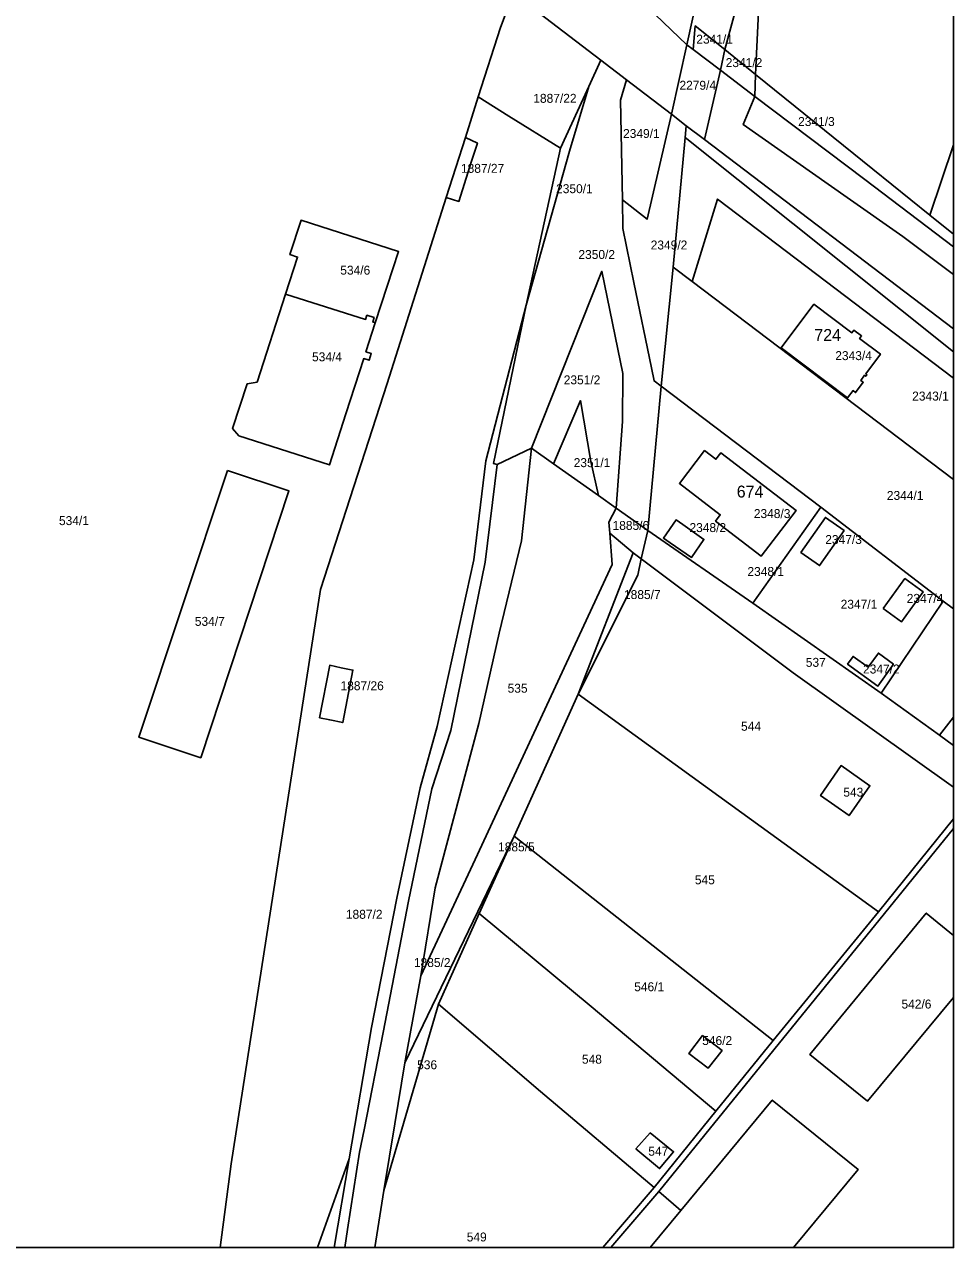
# Model space of a CAD drawing. Extents: x -561316 to -560969, y -1077679 to -1077341.
# Drawn here: x -561124.4 to -560968.7, y -1077679.3 to -1077474.3 of the extents above; entities that cross this region are included whole.
import ezdxf

# ---------------------------------------------------------------- set-up
doc = ezdxf.new("R2010")
doc.units = 0
for name, color, linetype in [('Adresní místo-text', 7, 'Continuous'), ('Parcela-polygon', 7, 'Continuous'), ('Parcela-text', 7, 'Continuous')]:
    doc.layers.add(name, color=color, linetype=linetype)

msp = doc.modelspace()

# ---------------------------------------------------------------- linework, layer by layer
at = {"layer": 'Parcela-polygon'}
for p, q in [((-560968.69, -1077494.47), (-560968.69, -1077454.77)), ((-560968.69, -1077509.45), (-560968.69, -1077494.47)), ((-560968.69, -1077511.52), (-560968.69, -1077509.45)), ((-560968.69, -1077516.19), (-560968.69, -1077511.52)), ((-560968.69, -1077525.27), (-560968.69, -1077516.19)), ((-560968.69, -1077529.13), (-560968.69, -1077525.27)), ((-560968.69, -1077533.59), (-560968.69, -1077529.13)), ((-560968.69, -1077550.53), (-560968.69, -1077533.59)), ((-560968.69, -1077572.24), (-560968.69, -1077550.53)), ((-560968.69, -1077590.42), (-560968.69, -1077572.24)), ((-560968.69, -1077595.14), (-560968.69, -1077590.42)), ((-560968.69, -1077602.11), (-560968.69, -1077595.14)), ((-560968.69, -1077607.47), (-560968.69, -1077602.11)), ((-560968.69, -1077609.05), (-560968.69, -1077607.47)), ((-560968.69, -1077627.01), (-560968.69, -1077609.05)), ((-560968.69, -1077637.4), (-560968.69, -1077627.01)), ((-561154.34, -1077679.32), (-561091.55, -1077679.32)), ((-561091.55, -1077679.32), (-561075.28, -1077679.32)), ((-561075.28, -1077679.32), (-561072.47, -1077679.32)), ((-561072.47, -1077679.32), (-561070.69, -1077679.32)), ((-561070.69, -1077679.32), (-561065.66, -1077679.32)), ((-561065.66, -1077679.32), (-561027.42, -1077679.32)), ((-561027.42, -1077679.32), (-561026.1, -1077679.32)), ((-561026.1, -1077679.32), (-561019.54, -1077679.32)), ((-561019.54, -1077679.32), (-560995.5, -1077679.32))]:
    msp.add_line(p, q, dxfattribs=at)
for points in [[(-561049.4, -1077448.02), (-561061.67, -1077436.19), (-561067.96, -1077422.91), (-561068.64, -1077418.05), (-561071.01, -1077414.57), (-561080.63, -1077400.23), (-561083.3, -1077402.66), (-561077.2, -1077431.15), (-561071.96, -1077441.19), (-561061.08, -1077454.04), (-561042.48, -1077469.05), (-561038.9, -1077471.78), (-561038.17, -1077472.34), (-561027.8, -1077480.27), (-561023.49, -1077483.56), (-561015.97, -1077489.32), (-561013.39, -1077477.66), (-561019.96, -1077471.39), (-561024.53, -1077467.03), (-561034.02, -1077457.97), (-561034.74, -1077457.28), (-561041.8, -1077454.56)], [(-560999.92, -1077421.13), (-561004.7, -1077438.43), (-561008.32, -1077441.67), (-561011.3, -1077441.2), (-561015.12, -1077440.58), (-561022.46, -1077462.15), (-561024.53, -1077467.03), (-561019.96, -1077471.39), (-561013.39, -1077477.66), (-561011.59, -1077469.52), (-561006.86, -1077448.2), (-561004.74, -1077446.51), (-560998.49, -1077422.25)], [(-561002.84, -1077444.99), (-561004.74, -1077446.51), (-561006.86, -1077448.2), (-561011.59, -1077469.52), (-561013.39, -1077477.66), (-561012.31, -1077478.48), (-561011.96, -1077474.5), (-561007.03, -1077478.49), (-561000.5, -1077454.6), (-561000.11, -1077443.84)], [(-561007.03, -1077478.49), (-561001.87, -1077482.65), (-561000.5, -1077454.6)], [(-561042.48, -1077469.05), (-561044.6, -1077474.75), (-561048.31, -1077486.41), (-561043.17, -1077489.63), (-561034.56, -1077495.01), (-561029.82, -1077484.67), (-561027.8, -1077480.27), (-561038.17, -1077472.34), (-561038.9, -1077471.78)], [(-561011.96, -1077474.5), (-561012.31, -1077478.48), (-561007.76, -1077481.93), (-561007.03, -1077478.49)], [(-561012.31, -1077478.48), (-561013.39, -1077477.66), (-561015.97, -1077489.32), (-561013.46, -1077491.24), (-561010.39, -1077493.57), (-561007.76, -1077481.93)], [(-561007.76, -1077481.93), (-561001.97, -1077486.32), (-561001.87, -1077482.65), (-561007.03, -1077478.49)], [(-561040.3, -1077521.34), (-561045.79, -1077547.85), (-561045.15, -1077548.03), (-561039.41, -1077545.32), (-561027.61, -1077515.65), (-561024.94, -1077528.68), (-561024.1, -1077532.76), (-561024.14, -1077540.85), (-561025.24, -1077555.34), (-561019.93, -1077559.09), (-561017.67, -1077534.93), (-561018.86, -1077534.02), (-561019.31, -1077531.84), (-561022.24, -1077517.52), (-561024.1, -1077508.46), (-561024.18, -1077503.66), (-561024.47, -1077486.94), (-561023.49, -1077483.56), (-561027.8, -1077480.27), (-561029.82, -1077484.67), (-561033.06, -1077495.53)], [(-561023.49, -1077483.56), (-561024.47, -1077486.94), (-561024.18, -1077503.66), (-561020.04, -1077506.91), (-561015.97, -1077489.32)], [(-561034.56, -1077495.01), (-561040.3, -1077521.34), (-561033.06, -1077495.53), (-561029.82, -1077484.67)], [(-561020.04, -1077506.91), (-561024.18, -1077503.66), (-561024.1, -1077508.46), (-561022.24, -1077517.52), (-561019.31, -1077531.84), (-561018.86, -1077534.02), (-561017.67, -1077534.93), (-561015.64, -1077514.95), (-561013.63, -1077493.22), (-561013.46, -1077491.24), (-561015.97, -1077489.32)], [(-561050.47, -1077493.22), (-561053.67, -1077503.25), (-561051.57, -1077503.92), (-561049.72, -1077498.1), (-561049.43, -1077497.19), (-561048.47, -1077494.15)], [(-561061.68, -1077512.35), (-561078, -1077507.1), (-561079.88, -1077512.86), (-561078.6, -1077513.27), (-561080.62, -1077519.46), (-561067.2, -1077523.73), (-561066.97, -1077523.03), (-561065.77, -1077523.41), (-561066.01, -1077524.13), (-561065.57, -1077524.27), (-561063.56, -1077518.16)], [(-561039.41, -1077545.32), (-561035.74, -1077547.92), (-561031.2, -1077537.32), (-561029.46, -1077547.55), (-561028.18, -1077553.26), (-561025.24, -1077555.34), (-561024.14, -1077540.85), (-561024.1, -1077532.76), (-561024.94, -1077528.68), (-561027.61, -1077515.65)], [(-561066.25, -1077529.44), (-561067.15, -1077529.15), (-561065.57, -1077524.27), (-561066.01, -1077524.13), (-561065.77, -1077523.41), (-561066.97, -1077523.03), (-561067.2, -1077523.73), (-561080.62, -1077519.46), (-561085.39, -1077534.21), (-561087.06, -1077534.53), (-561089.47, -1077542.01), (-561088.41, -1077543.24), (-561073.26, -1077548.12), (-561070.5, -1077539.52), (-561067.51, -1077530.27), (-561066.6, -1077530.56)], [(-560985.38, -1077525.51), (-560985.71, -1077525.95), (-560992.07, -1077521.16), (-560997.57, -1077528.47), (-560986.43, -1077536.87), (-560985.53, -1077535.66), (-560985.11, -1077535.97), (-560983.82, -1077534.25), (-560984.24, -1077533.94), (-560983.59, -1077533.08), (-560983.39, -1077533.25), (-560983.2, -1077532.98), (-560983.39, -1077532.82), (-560980.94, -1077529.54), (-560984.42, -1077526.92), (-560984.09, -1077526.48)], [(-561017.67, -1077534.93), (-561019.93, -1077559.09), (-561002.33, -1077571.3), (-560990.94, -1077555.2)], [(-561031.2, -1077537.32), (-561035.74, -1077547.92), (-561028.18, -1077553.26), (-561029.46, -1077547.55)], [(-561026.45, -1077557.71), (-561025.24, -1077555.34), (-561028.18, -1077553.26), (-561035.74, -1077547.92), (-561039.41, -1077545.32), (-561041.08, -1077560.86), (-561044.81, -1077576.33), (-561048.24, -1077591.47), (-561055.56, -1077618.99), (-561057.92, -1077633.79), (-561048.86, -1077614.29), (-561025.87, -1077564.82), (-561026.3, -1077559.58)], [(-561014.61, -1077551.21), (-561010.4, -1077545.71), (-561008.49, -1077547.17), (-561007.68, -1077546.09), (-560995.08, -1077555.74), (-561000.94, -1077563.41), (-561008.56, -1077557.54), (-561007.78, -1077556.47)], [(-561008.49, -1077547.17), (-561010.4, -1077545.71), (-561014.61, -1077551.21), (-561007.78, -1077556.47), (-561008.56, -1077557.54), (-561000.94, -1077563.41), (-560995.08, -1077555.74), (-561007.68, -1077546.09)], [(-561090.35, -1077549.03), (-561105.17, -1077593.77), (-561094.83, -1077597.2), (-561080.04, -1077552.47)], [(-561025.24, -1077555.34), (-561026.45, -1077557.71), (-561026.3, -1077559.58), (-561022.35, -1077562.87), (-561021.01, -1077563.88), (-561019.93, -1077559.09)], [(-561002.33, -1077571.3), (-560980.81, -1077586.39), (-560970.44, -1077570.95), (-560990.94, -1077555.2)], [(-561012.59, -1077563.63), (-561016.16, -1077561.18), (-561017.3, -1077560.39), (-561015.17, -1077557.33), (-561014.04, -1077558.12), (-561010.5, -1077560.61)], [(-561015.17, -1077557.33), (-561017.3, -1077560.39), (-561016.16, -1077561.18), (-561012.59, -1077563.63), (-561010.5, -1077560.61), (-561014.04, -1077558.12)], [(-560987.03, -1077559.11), (-560991.13, -1077564.98), (-560994.25, -1077562.77), (-560990.16, -1077556.92)], [(-560994.25, -1077562.77), (-560991.13, -1077564.98), (-560987.03, -1077559.11), (-560990.16, -1077556.92)], [(-561048.86, -1077614.29), (-561057.92, -1077633.79), (-561060.6, -1077648.34), (-561042.32, -1077610.36), (-561031.57, -1077586.54), (-561022.35, -1077562.87), (-561026.3, -1077559.58), (-561025.87, -1077564.82)], [(-561022.35, -1077562.87), (-561031.57, -1077586.54), (-561021.61, -1077566.57), (-561021.01, -1077563.88)], [(-560980.47, -1077572.19), (-560976.83, -1077567.17), (-560973.76, -1077569.39), (-560977.39, -1077574.41)], [(-560980.47, -1077572.19), (-560977.39, -1077574.41), (-560973.76, -1077569.39), (-560976.83, -1077567.17)], [(-560981.37, -1077585.19), (-560986.44, -1077581.49), (-560985.51, -1077580.21), (-560983.01, -1077582.04), (-560981.27, -1077579.66), (-560978.75, -1077581.53)], [(-560986.44, -1077581.49), (-560981.37, -1077585.19), (-560978.75, -1077581.53), (-560981.27, -1077579.66), (-560983.01, -1077582.04), (-560985.51, -1077580.21)], [(-561074.93, -1077590.51), (-561073.21, -1077590.87), (-561071.02, -1077591.32), (-561069.31, -1077582.52), (-561071.29, -1077582.11), (-561073.21, -1077581.71)], [(-561008.03, -1077603.66), (-561031.57, -1077586.54), (-561042.32, -1077610.36), (-561021.9, -1077626.43), (-560998.9, -1077644.59), (-560981.28, -1077623.05)], [(-560990.97, -1077603.55), (-560986.18, -1077606.89), (-560982.7, -1077601.89), (-560987.52, -1077598.53)], [(-561064.14, -1077669.78), (-561055, -1077638.52), (-561048.19, -1077623.34), (-561042.32, -1077610.36), (-561060.6, -1077648.34), (-561062.29, -1077658.56)], [(-561021.9, -1077626.43), (-561042.32, -1077610.36), (-561048.19, -1077623.34), (-561029.43, -1077638.93), (-561008.51, -1077656.44), (-560998.9, -1077644.59)], [(-561029.43, -1077638.93), (-561048.19, -1077623.34), (-561055, -1077638.52), (-561037.9, -1077653.16), (-561018.85, -1077669.25), (-561008.51, -1077656.44)], [(-561009.82, -1077649.25), (-561013.05, -1077646.78), (-561010.74, -1077643.79), (-561007.47, -1077646.31)], [(-561010.74, -1077643.79), (-561013.05, -1077646.78), (-561009.82, -1077649.25), (-561007.47, -1077646.31)], [(-561021.9, -1077662.77), (-561017.93, -1077666.08), (-561015.59, -1077663.27), (-561019.5, -1077660.1)], [(-561015.59, -1077663.27), (-561017.93, -1077666.08), (-561021.9, -1077662.77), (-561019.5, -1077660.1)]]:
    msp.add_lwpolyline(points, close=True, dxfattribs=at)
for points in [[(-561091.55, -1077679.32), (-561089.7, -1077665.29), (-561074.75, -1077568.98), (-561063.6, -1077534.48), (-561053.67, -1077503.25), (-561050.47, -1077493.22), (-561048.31, -1077486.41), (-561044.6, -1077474.75), (-561042.48, -1077469.05), (-561061.08, -1077454.04), (-561071.96, -1077441.19), (-561077.2, -1077431.15), (-561083.3, -1077402.66), (-561097.85, -1077410.62), (-561118.92, -1077426.82), (-561123.47, -1077428.97), (-561141.46, -1077444.02)], [(-560968.69, -1077454.77), (-560988.77, -1077442.39), (-560995.41, -1077441.87), (-560997.54, -1077442.76), (-561000.5, -1077454.6), (-561001.87, -1077482.65), (-560982.23, -1077498.52), (-560972.64, -1077506.26), (-560968.69, -1077494.47)], [(-560968.69, -1077516.19), (-560977.16, -1077509.84), (-560986.49, -1077503.29), (-561003.96, -1077491.02), (-561001.97, -1077486.32), (-561007.76, -1077481.93), (-561010.39, -1077493.57), (-560968.69, -1077525.27)], [(-560968.69, -1077509.45), (-560972.64, -1077506.26), (-560982.23, -1077498.52), (-561001.87, -1077482.65), (-561001.97, -1077486.32), (-560983.57, -1077500.25), (-560968.69, -1077511.52)], [(-560968.69, -1077511.52), (-560983.57, -1077500.25), (-561001.97, -1077486.32), (-561003.96, -1077491.02), (-560986.49, -1077503.29), (-560977.16, -1077509.84), (-560968.69, -1077516.19)], [(-561075.28, -1077679.32), (-561069.95, -1077664.47), (-561066.21, -1077642.45), (-561061.99, -1077620.72), (-561058.03, -1077602.23), (-561055.23, -1077591.99), (-561049.05, -1077564.01), (-561047.07, -1077547.44), (-561040.3, -1077521.34), (-561034.56, -1077495.01), (-561043.17, -1077489.63), (-561048.31, -1077486.41), (-561050.47, -1077493.22), (-561048.47, -1077494.15), (-561049.43, -1077497.19), (-561049.72, -1077498.1), (-561051.57, -1077503.92), (-561053.67, -1077503.25), (-561063.6, -1077534.48), (-561074.75, -1077568.98), (-561089.7, -1077665.29), (-561091.55, -1077679.32)], [(-560968.69, -1077525.27), (-561010.39, -1077493.57), (-561013.46, -1077491.24), (-561013.63, -1077493.22), (-560968.69, -1077529.13)], [(-560968.69, -1077529.13), (-561013.63, -1077493.22), (-561015.64, -1077514.95), (-561012.48, -1077517.35), (-561008.23, -1077503.55), (-560968.69, -1077533.59)], [(-560968.69, -1077494.47), (-560972.64, -1077506.26), (-560968.69, -1077509.45)], [(-560968.69, -1077533.59), (-561008.23, -1077503.55), (-561012.48, -1077517.35), (-560968.69, -1077550.53)], [(-561078, -1077507.1), (-561061.68, -1077512.35), (-561063.56, -1077518.16), (-561065.57, -1077524.27), (-561067.15, -1077529.15), (-561066.25, -1077529.44), (-561066.6, -1077530.56), (-561067.51, -1077530.27), (-561070.5, -1077539.52), (-561073.26, -1077548.12), (-561088.41, -1077543.24), (-561089.47, -1077542.01), (-561087.06, -1077534.53), (-561085.39, -1077534.21), (-561080.62, -1077519.46), (-561078.6, -1077513.27), (-561079.88, -1077512.86), (-561078, -1077507.1)], [(-560968.69, -1077550.53), (-561012.48, -1077517.35), (-561015.64, -1077514.95), (-561017.67, -1077534.93), (-560990.94, -1077555.2), (-560970.44, -1077570.95), (-560968.69, -1077572.24)], [(-560984.09, -1077526.48), (-560984.42, -1077526.92), (-560980.94, -1077529.54), (-560983.39, -1077532.82), (-560983.2, -1077532.98), (-560983.39, -1077533.25), (-560983.59, -1077533.08), (-560984.24, -1077533.94), (-560983.82, -1077534.25), (-560985.11, -1077535.97), (-560985.53, -1077535.66), (-560986.43, -1077536.87), (-560997.57, -1077528.47), (-560992.07, -1077521.16), (-560985.71, -1077525.95), (-560985.38, -1077525.51), (-560984.09, -1077526.48)], [(-561070.69, -1077679.32), (-561070.22, -1077676.28), (-561068.21, -1077663.34), (-561067.46, -1077659.56), (-561064.23, -1077643.29), (-561060, -1077621.24), (-561056.11, -1077602.43), (-561052.89, -1077592.64), (-561047.16, -1077564.4), (-561045.15, -1077548.03), (-561045.79, -1077547.85), (-561040.3, -1077521.34), (-561047.07, -1077547.44), (-561049.05, -1077564.01), (-561055.23, -1077591.99), (-561058.03, -1077602.23), (-561061.99, -1077620.72), (-561066.21, -1077642.45), (-561069.95, -1077664.47), (-561072.47, -1077679.32)], [(-561065.66, -1077679.32), (-561064.14, -1077669.78), (-561062.29, -1077658.56), (-561060.6, -1077648.34), (-561057.92, -1077633.79), (-561055.56, -1077618.99), (-561048.24, -1077591.47), (-561044.81, -1077576.33), (-561041.08, -1077560.86), (-561039.41, -1077545.32), (-561045.15, -1077548.03), (-561047.16, -1077564.4), (-561052.89, -1077592.64), (-561056.11, -1077602.43), (-561060, -1077621.24), (-561064.23, -1077643.29), (-561067.46, -1077659.56), (-561068.21, -1077663.34), (-561070.22, -1077676.28), (-561070.69, -1077679.32)], [(-561090.35, -1077549.03), (-561080.04, -1077552.47), (-561094.83, -1077597.2), (-561105.17, -1077593.77), (-561090.35, -1077549.03)], [(-560968.69, -1077595.14), (-560971.06, -1077593.43), (-560980.81, -1077586.39), (-561002.33, -1077571.3), (-561019.93, -1077559.09), (-561021.01, -1077563.88), (-560995.54, -1077582.99), (-560968.69, -1077602.11)], [(-560968.69, -1077602.11), (-560995.54, -1077582.99), (-561021.01, -1077563.88), (-561021.61, -1077566.57), (-561031.57, -1077586.54), (-561008.03, -1077603.66), (-560981.28, -1077623.05), (-560968.69, -1077607.47)], [(-560968.69, -1077572.24), (-560970.44, -1077570.95), (-560980.81, -1077586.39), (-560971.06, -1077593.43), (-560968.69, -1077590.42)], [(-561074.93, -1077590.51), (-561073.21, -1077581.71), (-561071.29, -1077582.11), (-561069.31, -1077582.52), (-561071.02, -1077591.32), (-561073.21, -1077590.87), (-561074.93, -1077590.51)], [(-560968.69, -1077590.42), (-560971.06, -1077593.43), (-560968.69, -1077595.14)], [(-560986.18, -1077606.89), (-560990.97, -1077603.55), (-560987.52, -1077598.53), (-560982.7, -1077601.89), (-560986.18, -1077606.89)], [(-560968.69, -1077607.47), (-560981.28, -1077623.05), (-560998.9, -1077644.59), (-561008.51, -1077656.44), (-561018.85, -1077669.25), (-561027.42, -1077679.32)], [(-561026.1, -1077679.32), (-561018.09, -1077669.9), (-560968.69, -1077609.05)], [(-560968.69, -1077609.05), (-561018.09, -1077669.9), (-561014.38, -1077673.09), (-560999.06, -1077654.59), (-560984.66, -1077666.25), (-560995.5, -1077679.32)], [(-560968.69, -1077627.01), (-560973.25, -1077623.25), (-560992.78, -1077646.93), (-560983.08, -1077654.78), (-560968.69, -1077637.4)], [(-560968.69, -1077637.4), (-560983.08, -1077654.78), (-560992.78, -1077646.93), (-560973.25, -1077623.25), (-560968.69, -1077627.01)], [(-560995.5, -1077679.32), (-560968.69, -1077679.32), (-560968.69, -1077637.4)], [(-561027.42, -1077679.32), (-561018.85, -1077669.25), (-561037.9, -1077653.16), (-561055, -1077638.52), (-561064.14, -1077669.78), (-561065.66, -1077679.32)], [(-560995.5, -1077679.32), (-560984.66, -1077666.25), (-560999.06, -1077654.59), (-561014.38, -1077673.09), (-561019.54, -1077679.32)], [(-561072.47, -1077679.32), (-561069.95, -1077664.47), (-561075.28, -1077679.32)], [(-561019.54, -1077679.32), (-561014.38, -1077673.09), (-561018.09, -1077669.9), (-561026.1, -1077679.32)]]:
    msp.add_lwpolyline(points, dxfattribs=at)

# ---------------------------------------------------------------- texts
at = {"layer": 'Adresní místo-text'}
for s, p in [('724', (-560992.01, -1077527.33)), ('674', (-561005.01, -1077553.58))]:
    msp.add_text(s, height=2, dxfattribs=at).set_placement(p)
at = {"layer": 'Parcela-text'}
for s, p in [('2341/1', (-561011.79, -1077477.48)), ('2341/2', (-561006.86, -1077481.41)), ('2279/4', (-561014.61, -1077485.21)), ('1887/22', (-561039.1, -1077487.4)), ('2341/3', (-560994.73, -1077491.29)), ('2349/1', (-561024.06, -1077493.3)), ('1887/27', (-561051.22, -1077499.14)), ('2350/1', (-561035.28, -1077502.55)), ('2349/2', (-561019.43, -1077511.99)), ('2350/2', (-561031.54, -1077513.58)), ('534/6', (-561071.44, -1077516.21)), ('534/4', (-561076.17, -1077530.74)), ('2343/4', (-560988.5, -1077530.54)), ('2351/2', (-561034, -1077534.6)), ('2343/1', (-560975.62, -1077537.32)), ('2351/1', (-561032.33, -1077548.48)), ('2344/1', (-560979.86, -1077553.98)), ('2348/3', (-561002.15, -1077557.02)), ('534/1', (-561118.57, -1077558.2)), ('1885/6', (-561025.82, -1077559.01)), ('2348/2', (-561012.93, -1077559.37)), ('2347/3', (-560990.18, -1077561.37)), ('2348/1', (-561003.22, -1077566.73)), ('1885/7', (-561023.9, -1077570.6)), ('2347/4', (-560976.53, -1077571.24)), ('2347/1', (-560987.6, -1077572.22)), ('534/7', (-561095.81, -1077575.09)), ('537', (-560993.44, -1077581.96)), ('2347/2', (-560983.85, -1077583.08)), ('1887/26', (-561071.4, -1077585.88)), ('535', (-561043.4, -1077586.3)), ('544', (-561004.29, -1077592.68)), ('543', (-560987.15, -1077603.73)), ('1885/5', (-561045, -1077612.9)), ('545', (-561012.03, -1077618.42)), ('1887/2', (-561070.5, -1077624.2)), ('1885/2', (-561059.1, -1077632.29)), ('546/1', (-561022.19, -1077636.35)), ('542/6', (-560977.41, -1077639.25)), ('546/2', (-561010.8, -1077645.37)), ('536', (-561058.56, -1077649.43)), ('548', (-561030.95, -1077648.5)), ('547', (-561019.83, -1077663.93)), ('549', (-561050.25, -1077678.3))]:
    msp.add_text(s, height=1.5, dxfattribs=at).set_placement(p)

doc.saveas('drawing.dxf')
